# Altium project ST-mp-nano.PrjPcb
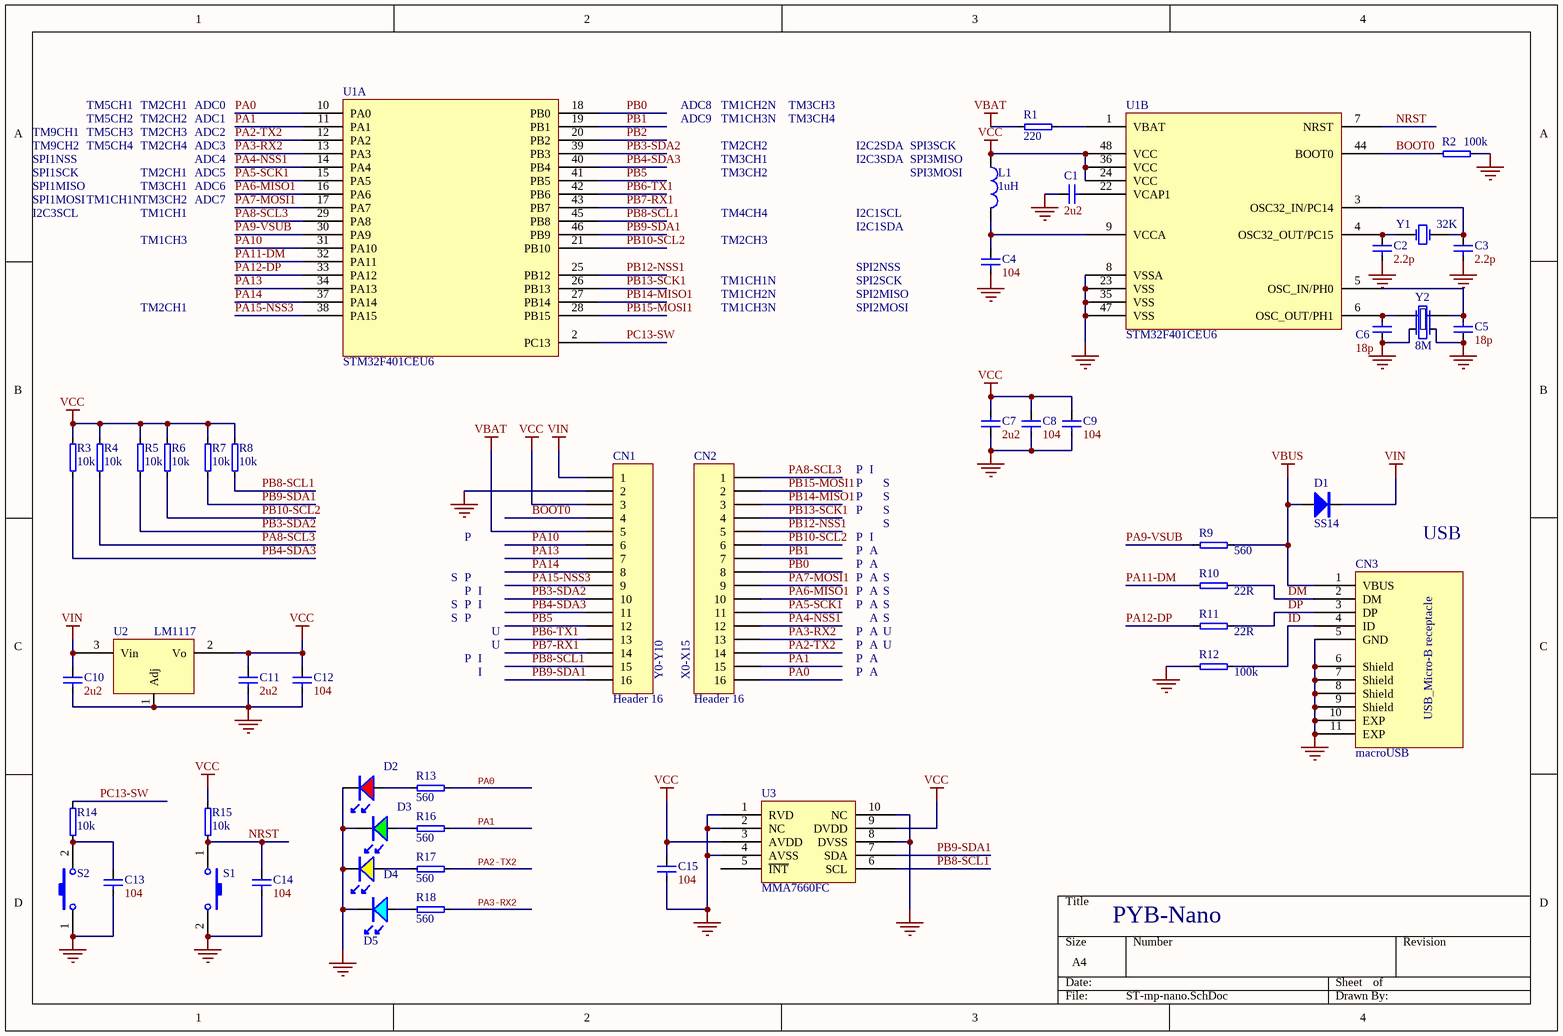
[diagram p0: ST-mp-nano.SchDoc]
1 sheet, 49 parts. Net scope: global (net labels, ports and power ports of the same name join across sheets).
Board file: ST-mp-nano.PcbDoc

## Sheet ST-mp-nano.SchDoc
size A4

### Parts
C1  2u2  [SMD0603]
C2  2.2p  [SMD0603]
C3  2.2p  [SMD0603]
C4  104  [SMD0603]
C5  18p  [SMD0603]
C6  18p  [SMD0603]
C7  2u2  [SMD0603]
C8  104  [SMD0603]
C9  104  [SMD0603]
C10  2u2  [SMD0603]
C11  2u2  [SMD0603]
C12  104  [SMD0603]
C13  104  [SMD0603]
C14  104  [SMD0603]
C15  104  [SMD0603]
CN1  Header 16  [HDR1X16]
CN2  Header 16  [HDR1X16]
CN3  macroUSB  [MOLEX_1050170001]
D1  SS14  [SS24 - small]
D2  LED RED  [LED0603]  (value not drawn)
D3  LED GREEN  [LED0603]  (value not drawn)
D4  LED Yellow  [LED0603]  (value not drawn)
D5  LED Blue  [LED0603]  (value not drawn)
L1  1uH  [SMD0603]
R1  220  [SMD0603]
R2  100k  [SMD0603]
R3  10k  [SMD0603]
R4  10k  [SMD0603]
R5  10k  [SMD0603]
R6  10k  [SMD0603]
R7  10k  [SMD0603]
R8  10k  [SMD0603]
R9  560  [SMD0603]
R10  22R  [SMD0603]
R11  22R  [SMD0603]
R12  100k  [SMD0603]
R13  560  [SMD0603]
R14  10k  [SMD0603]
R15  10k  [SMD0603]
R16  560  [SMD0603]
R17  560  [SMD0603]
R18  560  [SMD0603]
S1  SW-RST  [SWPB_2x4_L]  (value not drawn)
S2  (no value)  [SWPB_2x4_L]
U1  STM32F401CEU6  [QFN48]  (parts A,B of 2)
U2  LM1117  [SOT223]
U3  MMA7660FC  [MMA7660]
Y1  32K  [TXC_9H03200019]
Y2  8M  [SMD3225]

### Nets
GND: C1.2 C2.1 C3.1 C4.1 C5.2 C6.2 C7.2 C8.1 C9.1 C10.1 C11.1 C12.1 C13.1 C14.1 C15.1 CN1.2 CN3.5(GND) CN3.6(Shield) CN3.7(Shield) CN3.8(Shield) CN3.9(Shield) CN3.10(EXP) CN3.11(EXP) D2.2 D3.2 D4.2 D5.2 R2.2 R12.1 S1.2 S2.1 U1.8(VSSA) U1.23(VSS) U1.35(VSS) U1.47(VSS) U2.1(Adj) U3.1(RVD) U3.2(NC) U3.4(AVSS) U3.8(DVSS) U3.10(NC) Y2.2(GND) Y2.4(GND)
VBAT: CN1.5 R1.1
VBUS: CN3.1(VBUS) D1.1 R9.2
VCC: C7.1 C8.2 C9.2 C11.2 C12.2 C15.2 CN1.3 L1.1 R3.1 R4.1 R5.1 R6.1 R7.1 R8.1 R15.2 U1.24(VCC) U1.36(VCC) U1.48(VCC) U2.2(Vo) U3.3(AVDD) U3.9(DVDD)
VIN: C10.2 CN1.1 D1.2 U2.3(Vin)
BOOT0: CN1.4 R2.1 U1.44(BOOT0)
DM: CN3.2(DM) R10.2
DP: CN3.3(DP) R11.2
ID: CN3.4(ID) R12.2
NRST: C14.2 R15.1 S1.1 U1.7(NRST)
PA0: CN2.16 R13.1 U1.10(PA0)
PA1: CN2.15 R16.1 U1.11(PA1)
PA2-TX2: CN2.14 R17.1 U1.12(PA2)
PA3-RX2: CN2.13 R18.1 U1.13(PA3)
PA4-NSS1: CN2.12 U1.14(PA4)
PA5-SCK1: CN2.11 U1.15(PA5)
PA6-MISO1: CN2.10 U1.16(PA6)
PA7-MOSI1: CN2.9 U1.17(PA7)
PA8-SCL3: CN2.1 R4.2 U1.29(PA8)
PA9-VSUB: R9.1 U1.30(PA9)
PA10: CN1.6 U1.31(PA10)
PA11-DM: R10.1 U1.32(PA11)
PA12-DP: R11.1 U1.33(PA12)
PA13: CN1.7 U1.34(PA13)
PA14: CN1.8 U1.37(PA14)
PA15-NSS3: CN1.9 U1.38(PA15)
PB0: CN2.8 U1.18(PB0)
PB1: CN2.7 U1.19(PB1)
PB2: U1.20(PB2)
PB3-SDA2: CN1.10 R5.2 U1.39(PB3)
PB4-SDA3: CN1.11 R3.2 U1.40(PB4)
PB5: CN1.12 U1.41(PB5)
PB6-TX1: CN1.13 U1.42(PB6)
PB7-RX1: CN1.14 U1.43(PB7)
PB8-SCL1: CN1.15 R8.2 U1.45(PB8) U3.6(SCL)
PB9-SDA1: CN1.16 R7.2 U1.46(PB9) U3.7(SDA)
PB10-SCL2: CN2.6 R6.2 U1.21(PB10)
PB12-NSS1: CN2.5 U1.25(PB12)
PB13-SCK1: CN2.4 U1.26(PB13)
PB14-MISO1: CN2.3 U1.27(PB14)
PB15-MOSI1: CN2.2 U1.28(PB15)
PC13-SW: R14.2 U1.2(PC13)
NetC1_1: C1.1 U1.22(VCAP1)
NetC2_2: C2.2 U1.4(OSC32_OUT/PC15) Y1.1(OSC1)
NetC3_2: C3.2 U1.3(OSC32_IN/PC14) Y1.2(OSC2)
NetC4_2: C4.2 L1.2 U1.9(VCCA)
NetC5_1: C5.1 U1.5(OSC_IN/PH0) Y2.3(OSC2)
NetC6_1: C6.1 U1.6(OSC_OUT/PH1) Y2.1(OSC1)
NetC13_2: C13.2 R14.1 S2.2
NetD2_1: D2.1 R13.2
NetD3_1: D3.1 R16.2
NetD4_1: D4.1 R17.2
NetD5_1: D5.1 R18.2
NetR1_2: R1.2 U1.1(VBAT)

Not connected (* = marked no-connect by the designer): U2 4; U3 5(~{INT})

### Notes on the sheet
- TM5CH1
- TM2CH1
- ADC0
- ADC8
- TM1CH2N
- TM3CH3
- TM9CH1
- TM9CH2
- SPI1NSS
- SPI1SCK
- TM5CH2
- TM5CH3
- TM5CH4
- TM2CH2
- TM2CH3
- TM2CH4
- ADC1
- ADC2
- ADC3
- ADC4
- ADC5
- ADC9
- TM1CH3N
- TM3CH1
- TM3CH2
- TM3CH4
- I2C2SDA
- I2C3SDA
- (near L1) SPI3MISO
- (near L1) SPI3MOSI
- (near L1) SPI3SCK
- SPI1MISO
- SPI1MOSI
- I2C3SCL
- TM1CH1N
- TM1CH1
- TM1CH3
- ADC6
- ADC7
- TM4CH4
- I2C1SCL
- I2C1SDA
- SPI2SCK
- SPI2NSS
- SPI2MISO
- SPI2MOSI
- P
- I
- S
- A
- USB
- U
- (near CN1) Y0-Y10
- (near CN2) X0-X15
- PYB-Nano

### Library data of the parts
C1-C15 = Cap
CN1 CN2 = Header 16: Header, 16-Pin
CN3 = 1050170001: Silkscreen: USB
D1 = Diode
D2 = LED-RED
D3 = LED-GREEN
D4 = LED-YELLOW
D5 = LED-BLUE
L1 = Inductor: Code_IEC: 1005
R1-R18 = Res
S1 S2 = SW-PB: Switch
U3 = MMA7660
Y1 = XTAL
Y2 = XTAL_SMD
